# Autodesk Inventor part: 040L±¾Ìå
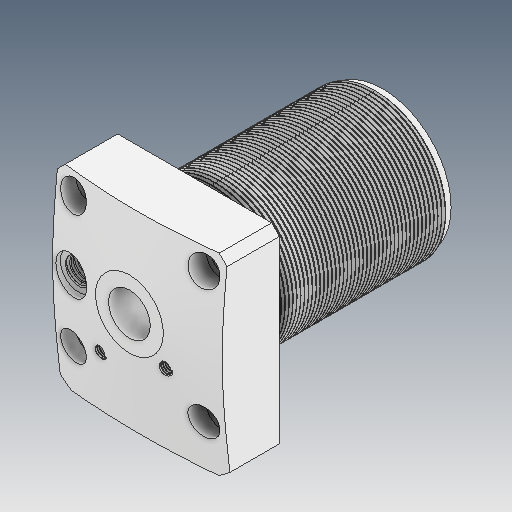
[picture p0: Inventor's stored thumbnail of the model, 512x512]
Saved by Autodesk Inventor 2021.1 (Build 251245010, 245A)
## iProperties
Created: 2021-06
Part Number: 040L±¾Ìå
Material: Ogólny
Document SubType Name: Modeling
Designer: user
Density: 1 g/cm^3
Appearance: Domyślna
Author: user
Revision Number: ÈÎºÎ
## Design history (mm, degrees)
feature "ÊäÈë1"
node "Bryła1"
